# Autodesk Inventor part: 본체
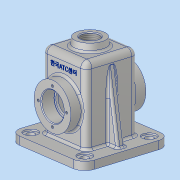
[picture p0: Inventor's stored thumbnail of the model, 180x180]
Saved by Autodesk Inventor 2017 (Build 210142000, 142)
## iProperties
Part Number: 본체
Material: 알루미늄 6061
Document SubType Name: Modeling
Designer: MRC
Density: 2.7 g/cm^3
Appearance: 알루미늄 - 평지
Mass: 748.788 g
Surface Area: 864.325 cm^2
Volume: 277.329 cm^3
Author: MRC
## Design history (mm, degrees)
sketch "스케치1"
  geometry: L1 (-34, 53)-(34, 53); L2 (34, 53)-(34, -52); L3 (34, -52)-(-34, -52); L4 (-34, -52)-(-34, 53); 2 further points
  constraints: 8 end point, 2 parallel, 1 horizontal, 1 midpoint, 1 perpendicular, 1 vertical alignment
  dimensions: "d0" = 68 distance of L2.end L3.end; "d1" = 105 distance of L1.end L2.end; "d2" = 52 distance from line of L3 point (0, 0)
extrude "돌출1" new body sketch "스케치1" stored distance "d3" = 68; taper "d4" = 0 deg
fillet "모깎기1" dims "d5" = 8
fillet "모깎기2" dims "d6" = 8
feature "쉘1" dims "d7" = 5
node "작업 평면1"
sketch "스케치2"
  geometry: C1 r 28.5 at (0, 0); 1 further point
  constraints: 1 centre point, 1 coincident
  dimensions: "d9" = 57 diameter of C1
extrude "돌출2" join sketch "스케치2" stored distance "d10" = 68; taper "d11" = 0 deg
sketch "스케치3"
  geometry: C1 r 28.5 at (0, 0) reference; C2 r 17.5 at (0, 0)
  constraints: 1 centre point, 1 coincident
  dimensions: "d12" = 35 diameter of C2
extrude "돌출3" cut sketch "스케치3" distance "d13" = 17; taper "d14" = 0 deg
sketch "스케치4"
  geometry: C1 r 17.5 at (0, 0) reference; C2 r 15 at (0, 0)
  constraints: 1 centre point, 1 coincident
  dimensions: "d15" = 30 diameter of C2
extrude "돌출4" cut sketch "스케치4" stored distance "d16" = 17; taper "d17" = 0 deg
sketch "스케치5"
  geometry: C1 r 17.5 at (0, 0) reference; 1 further point
  constraints: 1 vertical alignment
  dimensions: "d74" = 22 distance of C1.centre point (0, 22)
hole "구멍1" sketch "스케치5" at (0, 22) diameter "d18" = 3.242; stored, may be unused: countersink angle "d22" = 90 deg, drill point angle "d24" = 118 deg; dims "d19" = 8, "d20" = 4, "d21" = 2, "d23" = 10
sketch "스케치6"
  geometry: C1 r 20 at (26, 26); 1 further point
  constraints: 1 centre point, 1 coincident
  dimensions: "d28" = 40 diameter of C1
extrude "돌출5" join sketch "스케치6" distance "d29" = 10; taper "d30" = 0 deg
sketch "스케치7"
  geometry: C1 r 20 at (0, 0) reference
hole "구멍2" sketch "스케치7" at (0, 0) diameter "d31" = 22.835; stored, may be unused: countersink angle "d35" = 90 deg, drill point angle "d37" = 118 deg; dims "d32" = 100, "d33" = 4, "d34" = 2, "d36" = 100
feature "면 기울기1" dims angle "d38" = 8 deg
sketch "스케치8"
  geometry: L1 (-8, 60)-(-8, 8) reference; L2 (52, 0)-(0, 0) reference; L3 (60, 60)-(60, 8) reference; L4 (0, 68)-(52, 68) reference; L5 (83, -23)-(-31, -23); L6 (-31, -23)-(-31, 91); L7 (-31, 91)-(83, 91); L8 (83, 91)-(83, -23); L9 (83, -23)-(-31, 91); L10 (-31, -23)-(83, 91); A1 r 8 centre (0, 60) between (0, 68) and (-8, 60) reference; A2 r 8 centre (0, 8) between (-8, 8) and (0, 0) reference; A3 r 8 centre (52, 8) between (52, 0) and (60, 8) reference; A4 r 8 centre (52, 60) between (60, 60) and (52, 68) reference; 1 further point
  constraints: 12 end point, 2 midpoint, 2 parallel, 1 horizontal, 1 perpendicular
  dimensions: "d39" = 114 distance of L6.end L7.end; "d40" = 114 distance of L5.end L6.end
extrude "돌출6" join sketch "스케치8" distance "d41" = 10; taper "d42" = 0 deg
fillet "모깎기3" dims "d43" = 15
sketch "스케치10"
  geometry: L1 (57, -42)-(57, -52) reference; L2 (42, -42)-(57, -42) reference; L3 (42.569, -5.525)-(49, -42); 1 further point
  constraints: 2 end point, 1 point on line
  dimensions: "d46" = 8 distance from line of L1 L3.end; "d47" = 10 deg angle of L1 L3
feature "리브1" sketch "스케치10" dims "d48" = 1, "d49" = 10, "d50" = 0, "d51" = 0, "d52" = 1, "d53" = 1
fillet "모깎기4" dims "d54" = 3
fillet "모깎기5" dims "d55" = 3
fillet "모깎기6" dims "d56" = 3
fillet "모깎기7" dims "d57" = 3
fillet "모깎기8" dims "d58" = 3
sketch "스케치11"
  geometry: A1 r 15 centre (68, 8) between (83, 8) and (68, 23) reference; A2 r 15 centre (-16, 8) between (-16, 23) and (-31, 8) reference; A3 r 15 centre (-16, -76) between (-31, -76) and (-16, -91) reference; A4 r 15 centre (68, -76) between (68, -91) and (83, -76) reference; 1 further point
hole "구멍3" sketch "스케치11" at (68, -76), (-16, -76), (-16, 8), (68, 8) diameter "d59" = 10; stored, may be unused: countersink angle "d63" = 90 deg, drill point angle "d65" = 118 deg; dims "d60" = 100, "d61" = 18, "d62" = 2, "d64" = 100
fillet "모깎기9" dims "d66" = 0.3
chamfer "모따기1" distance "d67" = 1; stored, may be unused: second distance "d68" = 2, angle "d69" = 45 deg
sketch "스케치12"
  geometry: L1 (-34, 45)-(-34, -39) reference; L2 (18.595, 63)-(-18.595, 63) reference; 1 further point
  constraints: 1 other
  dimensions: "d70" = 34 distance from line of L1 point (0, 38); "d71" = 25 distance from line of point (0, 38) L2
feature "엠보싱1" sketch "스케치12" dims "d0" = 68, "d1" = 105, "d2" = 52, "d72" = 0.5, "d73" = 0
chamfer "모따기2" distance "d75" = 1; stored, may be unused: second distance "d76" = 2, angle "d77" = 45 deg
node "솔리드1"
pattern_circular "원형 패턴1" dims angle "d26" = 360 deg
mirror "미러1"
mirror "미러2"
other parameters: "d8" = 15
